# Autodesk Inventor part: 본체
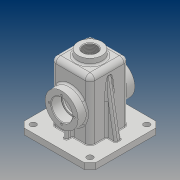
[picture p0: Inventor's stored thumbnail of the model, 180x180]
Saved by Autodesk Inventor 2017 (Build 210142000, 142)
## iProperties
Part Number: 본체
Material: 일반
Document SubType Name: Modeling
Designer: 20
Density: 1 g/cm^3
Appearance: 기본값
Author: 20
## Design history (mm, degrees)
sketch "스케치1"
  geometry: L1 (-32.5, -32.5)-(32.5, -32.5); L2 (32.5, -32.5)-(32.5, 32.5); L3 (32.5, 32.5)-(-32.5, 32.5); L4 (-32.5, 32.5)-(-32.5, -32.5); L5 (-32.5, -32.5)-(32.5, 32.5); L6 (32.5, -32.5)-(-32.5, 32.5); 1 further point
  constraints: 12 end point, 2 midpoint, 2 parallel, 1 horizontal, 1 perpendicular
  dimensions: "d0" = 65 distance of L3.end L2.end; "d1" = 65 distance of L2.end L1.end
extrude "돌출1" new body sketch "스케치1" stored distance "d2" = 110; taper "d3" = 0 deg
fillet "모깎기1" dims "d4" = 8
feature "쉘1" dims "d5" = 5
sketch "스케치2"
  geometry: L1 (60, -60)-(-60, -60); L2 (-60, -60)-(-60, 60); L3 (-60, 60)-(60, 60); L4 (60, 60)-(60, -60); L5 (60, -60)-(-60, 60); L6 (-60, -60)-(60, 60); L7 (-27.5, -24.5)-(-27.5, 24.5) reference; L8 (24.5, -27.5)-(-24.5, -27.5) reference; L9 (27.5, 24.5)-(27.5, -24.5) reference; L10 (-24.5, 27.5)-(24.5, 27.5) reference; A1 r 3 centre (-24.5, -24.5) between (-27.5, -24.5) and (-24.5, -27.5) reference; A2 r 3 centre (24.5, -24.5) between (24.5, -27.5) and (27.5, -24.5) reference; A3 r 3 centre (24.5, 24.5) between (27.5, 24.5) and (24.5, 27.5) reference; A4 r 3 centre (-24.5, 24.5) between (-24.5, 27.5) and (-27.5, 24.5) reference; 1 further point
  constraints: 12 end point, 2 midpoint, 2 parallel, 1 horizontal, 1 perpendicular
  dimensions: "d6" = 120 distance of L2.end L3.end; "d7" = 120 distance of L1.end L2.end
extrude "돌출2" join sketch "스케치2" distance "d8" = 10; taper "d9" = 0 deg
sketch "스케치3"
  geometry: L1 (-60, -45)-(60, -45) reference; L2 (48, -45)-(36.539, 20); L3 (60, -55)-(60, -45) reference; 1 further point
  constraints: 2 end point, 1 point on line
  dimensions: "d10" = 12 distance from line of L3 L2.start; "d11" = 10 deg angle of L3 L2; "d12" = 65 vertical distance of L2.start L2.end
feature "리브1" sketch "스케치3" dims "d13" = 1, "d14" = 10, "d15" = 0, "d16" = 0, "d17" = 1, "d18" = 1
node "작업 평면1"
sketch "스케치5"
  geometry: C1 r 27.5 at (24.5, -47); 1 further point
  constraints: 1 centre point, 1 coincident
  dimensions: "d23" = 55 diameter of C1
extrude "돌출4" join sketch "스케치5" stored distance "d24" = 15; taper "d25" = 0 deg
hole "구멍1" diameter "d28" = 30; stored, may be unused: countersink angle "d32" = 90 deg, drill point angle "d34" = 118 deg; dims "d26" = 10, "d27" = 10, "d29" = 6, "d30" = 35, "d31" = 17, "d33" = 8
sketch "스케치6"
  geometry: 2 further points
  constraints: 1 vertical alignment
  dimensions: "d35" = 21 distance of point (0, 0) point (0, 21)
hole "구멍2" sketch "스케치6" at (0, 21) diameter "d36" = 3.242; stored, may be unused: countersink angle "d40" = 90 deg, drill point angle "d42" = 118 deg; dims "d37" = 8, "d38" = 35, "d39" = 17, "d41" = 10
node "작업 평면2"
sketch "스케치7"
  geometry: C1 r 20 at (0, 0); 1 further point
  constraints: 1 centre point, 1 coincident
  dimensions: "d47" = 40 diameter of C1
extrude "돌출5" join sketch "스케치7" stored distance "d48" = 15; taper "d49" = 5 deg
hole "구멍3" diameter "d52" = 22.835; stored, may be unused: countersink angle "d56" = 90 deg, drill point angle "d58" = 118 deg; dims "d50" = 10, "d51" = 10, "d53" = 50, "d54" = 35, "d55" = 17, "d57" = 59.3
sketch "스케치8"
  geometry: L1 (0, 39.5)-(0, -39.5); L2 (24.5, 27.5)-(-24.5, 27.5) reference; L3 (-24.5, -27.5)-(24.5, -27.5) reference; L4 (-3, 39.5)-(-3, 27.5); L5 (-3, -27.5)-(-3, -39.5); L6 (3, -39.5)-(3, -27.5); L7 (3, 27.5)-(3, 39.5); A1 r 3 centre (0, 39.5) between (3, 39.5) and (-3, 39.5); A2 r 3 centre (0, -39.5) between (-3, -39.5) and (3, -39.5); 3 further points
  constraints: 12 end point, 8 tangent, 5 point on circle, 4 parallel, 4 point on line, 2 centre point, 1 coincident, 1 midpoint, 1 vertical, 1 vertical alignment
  dimensions: "d59" = 6 diameter of A2; "d60" = 12 distance from line of L2 L1.start; "d61" = 15 distance from line of point (0, -42.5) L3 (derived)
extrude "돌출6" join sketch "스케치8" stored distance "d62" = 15; taper "d63" = 0 deg; dims "d6" = 120, "d7" = 120
chamfer "모따기1" distance "d64" = 10; stored, may be unused: second distance "d65" = 2, angle "d66" = 45 deg
sketch "스케치9"
  geometry: L1 (-60, 50)-(-60, -50) reference; L2 (-50, -60)-(50, -60) reference; C1 r 5 at (-47.5, -47.5); C2 r 5 at (-47.5, 47.5); C3 r 5 at (47.5, -47.5); C4 r 5 at (47.5, 47.5); 1 further point
  constraints: 4 centre point, 1 horizontal, 1 vertical, 6 other
  dimensions: "d67" = 10 diameter of C1; "d68" = 12.5 distance from line of L1 C1.centre; "d69" = 12.5 distance from line of L2 C1.centre; "d72" = 95 distance of C1.centre C2.centre; "d75" = 95 distance of C1.centre C3.centre
extrude "돌출7" cut sketch "스케치9" stored distance "d78" = 10; taper "d79" = 0 deg
fillet "모깎기2" dims "d80" = 3
fillet "모깎기3" dims "d81" = 3
fillet "모깎기4" dims "d82" = 1
fillet "모깎기5" dims "d83" = 0.3
node "작업 평면3"
sketch "스케치10"
  geometry: L1 (44.5, -18)-(4.5, -18) reference; L2 (57, 0)-(57, 91) reference; 2 further points
  constraints: 1 other
  dimensions: "d85" = 26 distance from line of point (24.5, 8) L1; "d86" = 32.5 distance from line of L2 point (24.5, 8)
feature "엠보싱1" sketch "스케치10" dims "d0" = 65, "d1" = 65, "d6" = 120, "d7" = 120, "d87" = 0.5, "d88" = 0
chamfer "모따기2" distance "d89" = 1; stored, may be unused: second distance "d90" = 2, angle "d91" = 45 deg
fillet "모깎기6" dims "d92" = 3
node "솔리드1"
mirror "미러1"
pattern_circular "원형 패턴1" dims angle "d44" = 360 deg
mirror "미러2"
other parameters: "d22" = 15, "d84" = 30.5
